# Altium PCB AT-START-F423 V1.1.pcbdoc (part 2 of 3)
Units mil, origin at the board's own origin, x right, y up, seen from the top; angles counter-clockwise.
Board outline 13392.89 x 3532.45 mil, 2 copper layers (Top Layer, Bottom Layer); 137 components, 162 nets, 618 pads, 618 vias.
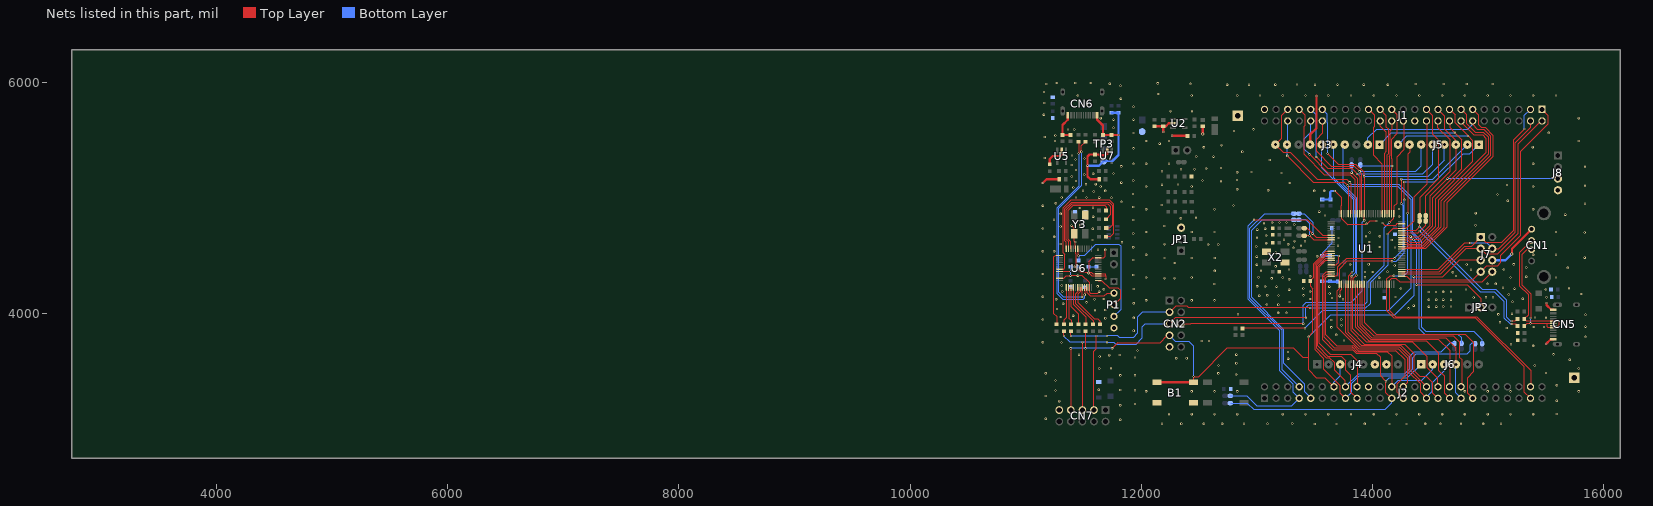
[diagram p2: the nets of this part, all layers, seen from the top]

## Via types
v1: diameter 19.68, hole 7.87, Top Layer to Bottom Layer, 317 vias
v2: diameter 19.7, hole 7.9, Top Layer to Bottom Layer, 187 vias
v3: diameter 19.7, hole 7.87, Top Layer to Bottom Layer, 72 vias
v4: diameter 27.56, hole 15.75, Top Layer to Bottom Layer, 31 vias
v5: diameter 23.62, hole 11.81, Top Layer to Bottom Layer, 11 vias

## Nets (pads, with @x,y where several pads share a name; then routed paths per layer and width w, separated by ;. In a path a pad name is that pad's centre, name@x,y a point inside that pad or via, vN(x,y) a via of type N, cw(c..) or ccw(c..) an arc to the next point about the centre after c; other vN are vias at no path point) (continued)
GND: B1.3 B1.4 C1.1 C2.1 C3.1 C7.1 C8.1 C9.1 C10.1 C11.1 C12.1 C14.1 C15.1 C16.1 C17.1 C18.1 C19.1 C20.1 C21.1 C22.1 C23.1 C24.1 C25.1 C26.1 C27.1 C29.1 C30.1 C31.1 C32.1 C33.1 C34.1 C35.1 C36.1 C37.1 C38.1 C39.1 CN1.4 CN2.9 CN5.A1B12 CN5.B1A12 CN6.A1B12 CN6.B1A12 CN7.9 D4.2 J1.24 J1.49 J2.20 J2.27 J3.7 J4.6 J4.7 J7.6 J8.4 JP1.3 LED1.2 P1.5 R2.1 R4.2 R7.1 R18.2 R19.2 R20.2 R21.2 R49.1 R51.1 R53.2 T1.1 T2.1 TP1.2 TP3.4 U1.20 U1.27 U1.74 U1.99 U2.2 U5.2 U6.8 U6.20 U6.23 U6.35 U6.39 U6.40 U6.47 U7.2 X2.2 X2.4 Y3.2 Y3.4 | length 7475.3
  Top Layer w6: U6.23@11292.68,4304.77 11327.37,4304.77 11350.28,4327.68 v1(11388.28,4327.68) v1(11451.38,4327.68) 11491.28,4327.68 11548.59,4270.36 U6.35@11548.58,4226.03 11548.59,4187.36 11559.28,4176.68 11623.28,4176.68 v1(11635.28,4188.68) ; U6.20@11292.68,4363.82 11388.13,4363.83 v1(11388.28,4363.68) ; U6.8@11430.47,4560.67 11430.48,4519.47 11434.28,4515.68 11434.28,4414.68 v1(11423.28,4403.68) 11476.28,4350.68 v5(11543.28,4350.68) ; v1(11689.28,4550.68) 11689.28,4495.68 11675.54,4481.94 U6.47@11627.32,4481.93 11579.54,4481.94 11543.28,4445.68 v5(11543.28,4350.68) ; v1(11690.28,4298.68) 11690.28,4324.46 ; v3(14085.58,4782.11) 14104.58,4763.11 14198.58,4763.11 14210.08,4774.61 U1.74@14251.67,4774.61 ; v5(11543.28,4350.68) 11569.5,4324.46 11627.32,4324.46 11690.28,4324.46 ; v5(11543.28,4350.68) 11573.28,4350.68 11579.82,4344.14 U6.40@11627.32,4344.14 11690.28,4344.14 11690.28,4324.46
  Top Layer w10: v1(11396.28,4759.68) 11421.04,4734.92 Y3.4@11421.04,4689.97 11421.04,4626.92 v1(11430.28,4617.68) 11430.48,4617.47 U6.8@11430.47,4560.67 ; U1.20@13641.48,4420.31 13683.77,4420.31 13707.58,4444.11 13707.58,4496.11 v1(13706.58,4497.11) ; v3(13671.58,5060.11) 13732.58,4999.11 13732.58,4934.11 13730.08,4931.61 U1.99@13730.08,4863.21 13730.08,4823.61 13784.58,4769.11 13944.58,4769.11 13974.58,4799.11 v2(14033.58,4799.11) ; v5(13715.58,4152.11) 13714.58,4153.11 13714.58,4191.11 13730.08,4206.61 U1.27@13730.08,4253.01
  Top Layer w20: v1(11148.28,5129.27) 11179.68,5160.68 C17.1@11290.72,5160.68 ; R51.1@11208.28,5290.34 11208.28,5336.68 11233.28,5361.68 11299.28,5361.68 11311.28,5373.68 U5.2@11311.28,5410.68 ; CN6.B1A12@11363.6,5715.38 11363.6,5675 11318.28,5629.68 C19.1@11318.28,5543.24 C18.1@11388.28,5543.24 ; CN6.A1B12@11617.4,5715.38 11617.4,5676.55 11668.28,5625.68 C15.1@11668.28,5543.24 C16.1@11743.28,5543.24 11802.84,5543.24 v1(11803.28,5543.68) ; C14.1@11635.72,5160.68 11560.28,5160.68 11535.28,5185.68 v1(11535.28,5278.32) 11535.28,5357.68 11552.94,5375.34 R49.1@11598.28,5375.34 11598.62,5375.68 11633.28,5375.68 11641.28,5367.68 11693.28,5367.68 11706.27,5380.67 U7.2@11706.27,5415.68 ; C1.1@12113.62,5618.94 C2.1@12188.62,5618.94 ; v3@12189.62,5570.16 C2.1@12189.62,5617.94 C2.1@12188.62,5618.94 ; v2(12264.58,5537.11) 12265.01,5536.68 R2.1@12398.62,5536.68 ; U2.2@12274.62,5644.5 12237.96,5644.5 12212.4,5618.94 C2.1@12188.62,5618.94 ; C3.1@12531.28,5618.12 12531.28,5553.41 v4(12531.58,5553.11) ; J3.7@13459.5,5460.43 13459.5,5547.04 13514.89,5602.43 v1(13514.89,5881.6) ; v4(15202.58,4515.11) 15204.58,4517.11 15204.58,4559.41 CN1.4@15374.55,4729.39 ; v2(15498.89,3736.6) 15540.41,3778.11 CN5.A1B12@15562.27,3778.11 ; v2(15503.89,4090.6) 15503.89,4072.6 15544.58,4031.91 CN5.B1A12@15562.27,4031.91
  Bottom Layer w6: v1(11388.28,4327.68) v1(11388.28,4363.68) C12.1@11388.28,4403.12 11422.72,4403.12 v1(11423.28,4403.68) 11457.72,4403.68 C22.1@11458.28,4403.12 ; v5(11543.28,4350.68) C9.1@11543.28,4403.12 C8.1@11613.28,4403.12
  Bottom Layer w10: C38.1@13563.58,4498.67 13563.58,4522.11 13647.01,4605.55 C39.1@13647.01,4741.11 ; C37.1@13631.58,4498.67 13705.01,4498.67 v1(13706.58,4497.11)
  Bottom Layer w20: v1(11535.28,5278.32) 11634.82,5278.32 TP3.4@11674.63,5318.13 11751.73,5318.13 11803.28,5369.68 v1(11803.28,5543.68) R21.2@11803.28,5736.02 R20.2@11743.28,5736.02 ; C36.1@13561.58,4277.55 C35.1@13629.58,4277.55 ; C38.1@13563.58,4498.67 C37.1@13631.58,4498.67 ; C30.1@13564.58,4985.67 C31.1@13634.58,4985.67 13632.58,4987.67 13632.58,5049.11 13643.58,5060.11 v3(13671.58,5060.11) ; C35.1@13630.58,4278.55 C35.1@13629.58,4277.55 ; C32.1@13701.01,4275.11 13632.01,4275.11 C35.1@13629.58,4277.55 ; J7.6@15034.51,4460.97 15148.44,4460.97 v4(15202.58,4515.11)
  other v1: 14146.88,3044.08 14292.94,3044.08 13498.88,3045.08 13686.88,3045.08 13930.88,3046.08 14453.88,3046.08 14587.77,3046.08 14764.88,3046.08 14955.88,3046.08 12177.88,3047.08 12345.88,3047.08 12540.33,3047.08 12699.21,3047.08 12887.88,3047.08 13090.68,3047.08 15109.88,3047.08 13304.88,3048.08 11817.88,3081.08 11173.28,3089.77 12238.67,3129.95 12435.52,3129.95 12632.37,3129.95 12829.22,3129.95 13222.92,3129.95 13419.77,3129.95 13616.62,3129.95 13813.47,3129.95 14010.32,3129.95 14207.17,3129.95 14404.02,3129.95 14600.87,3129.95 14797.72,3129.95 14994.58,3129.95 15191.43,3129.95 15388.28,3129.95 15591.89,3131.6 11817.88,3207.08 11944.88,3218.08 11290.38,3241.98 15591.89,3245.6 11173.28,3286.62 12041.82,3326.8 12238.67,3326.8 12435.52,3326.8 12632.37,3326.8 12829.22,3326.8 14797.72,3326.8 14994.58,3326.8 15191.43,3326.8 15781.98,3326.8 11257.88,3335.08 11944.88,3336.08 11818.88,3339.17 11631.53,3341.08 15592.89,3379.6 11257.88,3419.98 11818.88,3465.08 11944.88,3465.08 12819.89,3473.6 11173.28,3483.47 12665.89,3482.6 11635.88,3524.08 15781.98,3523.66 11736.89,3527.6 12666.89,3549.6 12821.89,3569.6 13269.89,3609.6 12301.89,3613.6 12391.89,3613.6 11945.88,3620.08 11639.88,3628.08 11722.88,3640.08 11813.88,3641.08 11460.88,3644.08 12821.89,3644.6 13268.89,3666.6 11967.88,3680.08 15388.28,3720.51 11309.88,3750.08 11148.28,3751.32 12522.89,3762.6 12585.89,3762.6 15840.89,3798.6 11933.88,3851.08 15393.89,3882.6 15480.89,3882.6 11148.28,3948.17 11689.28,3958.68 11933.88,3962.48 15498.89,3962.6 15404.89,3964.6 11304.28,3969.68 11410.28,3981.68 15840.89,3989.6 12836.89,3993.6 13182.89,4005.6 13255.89,4005.6 11600.28,4028.68 11689.28,4030.68 11270.28,4039.68 14309.89,4044.6 14354.89,4067.6 11324.28,4084.68 11934.88,4089.08 11525.28,4096.68 12041.82,4114.21 12435.52,4114.21 12632.37,4114.21 11263.28,4123.68 11594.28,4123.68 11676.28,4124.68 15297.89,4127.6 11148.28,4145.02 15802.89,4169.6 11316.28,4190.68 11676.28,4209.68 11934.88,4211.45 15225.89,4214.6 13400.58,4217.11 11622.28,4234.68 11312.28,4242.68 12630.89,4255.6 12041.82,4311.06 12435.52,4311.06 13222.92,4311.06 15191.43,4311.06 15585.13,4311.06 13012.89,4313.6 11930.88,4333.08 11148.28,4341.87 11929.88,4462.08 12435.89,4479.6 12633.89,4479.6 12041.82,4507.91 15388.28,4507.91 15585.13,4507.91 11148.28,4538.72 11246.28,4538.68 11625.28,4551.68 11929.88,4572.71 12664.89,4596.6 11303.28,4600.68 11832.28,4615.68 11577.38,4636.13 11246.28,4662.69 11929.88,4692.08 12041.82,4704.76 12435.52,4704.76 12632.37,4704.76 15585.13,4704.76 13002.58,4725.11 11580.28,4732.68 11148.28,4735.57 11302.28,4751.68 11472.78,4766.2 13322.58,4769.11 11929.88,4808.94 11244.28,4810.68 11583.28,4837.68 11302.28,4861.45 14890.89,4867.6 12041.82,4901.61 12632.37,4901.61 15388.28,4901.61 11468.58,4913.11 11581.58,4914.11 11930.88,4920.08 11148.28,4932.42 12796.89,4934.6 11261.28,4953.68 11828.28,4965.68 11741.58,5001.11 11636.58,5002.11 11434.58,5003.11 11526.58,5003.11 11311.28,5003.68 15079.89,5028.6 11928.88,5033.08 11588.28,5055.68 11689.28,5060.68 11496.28,5061.68 12828.89,5074.6 11412.28,5089.68 11648.12,5098.46 12041.82,5098.46 12435.52,5098.46 15388.28,5098.46 15161.89,5111.6 11521.28,5116.68 11605.28,5118.68 13283.89,5127.6 11827.28,5131.68 11434.28,5146.68 11929.88,5150.08 11398.28,5185.68 11506.28,5201.68 11583.28,5208.68 11759.28,5210.68 11434.28,5240.84 11826.28,5272.68 11398.28,5283.68 11932.88,5294.08 12041.82,5295.31 12238.67,5295.31 15388.28,5295.31 13109.58,5327.11 11430.28,5332.68 11509.28,5339.68 11163.89,5345.6 11400.28,5366.68 11932.88,5428.08 11254.42,5492.16 12041.82,5492.16 12238.67,5492.16 15781.98,5492.16 11163.89,5525.6 11256.28,5539.68 11932.88,5560.94 11366.28,5590.68 11419.64,5590.68 11759.25,5606.03 11931.88,5676.08 11759.25,5676.58 11648.12,5689.01 15781.98,5689.01 11156.89,5719.6 11931.88,5788.08 11160.89,5820.6 11823.28,5857.68 11451.27,5885.86 12435.52,5885.86 12829.22,5885.86 13026.07,5885.86 13222.92,5885.86 13419.77,5885.86 13616.62,5885.86 13813.47,5885.86 14010.32,5885.86 14207.17,5885.86 14404.02,5885.86 14600.87,5885.86 14797.72,5885.86 14994.58,5885.86 15191.43,5885.86 15388.28,5885.86 15585.13,5885.86 12145.58,5898.11 11157.89,5915.6 11819.28,5969.68 12741.88,5979.08 12931.88,5979.08 13158.88,5979.08 13500.88,5979.08 13696.88,5979.08 13922.96,5979.08 14131.88,5979.08 13346.88,5981.08 11178.28,5983.68 14372.88,5984.08 14614.8,5984.08 14812.88,5984.08 15038.88,5984.08 12425.13,5986.13 11727.28,5986.68 12141.88,5990.08 11429.28,5992.68 11563.56,5992.68 11269.28,5993.68
  other v2: 15498.58,3486.11 15401.58,3550.11 15704.58,3600.11 15563.58,3647.11 15196.58,3734.11 13751.89,3766.6 13685.89,3815.6 15158.89,3874.6 13642.89,3880.6 15840.58,3886.11 13730.89,3898.6 15100.89,3923.6 13641.89,3944.6 13728.89,3948.6 15086.89,3992.6 15204.89,3998.6 14485.89,4059.6 14549.89,4059.6 14610.89,4060.6 14677.89,4060.6 13184.58,4076.11 13085.58,4078.11 13280.58,4099.11 15209.89,4101.6 14485.89,4118.6 14549.89,4118.6 14610.89,4119.6 14677.89,4119.6 13744.58,4123.11 13459.58,4125.11 13647.89,4133.6 14873.89,4138.6 14979.89,4139.6 15040.89,4140.6 15503.89,4140.6 14197.89,4142.6 13019.89,4153.6 13186.58,4155.11 13402.58,4157.11 13088.58,4158.11 15176.89,4164.6 13628.58,4172.11 14484.89,4186.6 14548.89,4186.6 14609.89,4187.6 14676.89,4187.6 13459.58,4190.42 13278.58,4206.68 14807.89,4207.6 15497.89,4208.6 14243.89,4216.6 15697.89,4219.6 15126.89,4222.6 13169.58,4232.11 13625.58,4232.11 13070.37,4233.11 13001.89,4234.6 14992.89,4256.6 15063.89,4256.6 13278.58,4296.11 13126.58,4304.11 12201.04,4306.11 12287.58,4306.11 14056.58,4309.11 13934.01,4312.5 15328.58,4317.69 13459.58,4322.11 14720.89,4324.6 14693.89,4356.6 13934.01,4358.11 14001.58,4358.11 14129.58,4361.11 12633.89,4368.6 13035.58,4369.11 14850.89,4378.6 13276.58,4380.11 15134.58,4380.11 15687.58,4395.11 15328.58,4398.11 13161.88,4408.18 14190.58,4415.11 12998.89,4422.6 13805.58,4424.11 14812.89,4424.6 15220.58,4425.11 13965.58,4426.11 12289.58,4436.11 12200.58,4479.11 15833.7,4482.65 12997.89,4491.6 13520.58,4495.11 13161.58,4526.11 13315.58,4568.11 14193.58,4571.11 14062.58,4575.84 12993.89,4578.6 13935.58,4581.11 13381.58,4585.11 13700.89,4585.6 12577.89,4596.6 13269.58,4599.11 12199.58,4600.11 13079.58,4608.11 13969.89,4618.6 13415.58,4625.11 13323.89,4625.6 14164.58,4636.11 13233.58,4638.11 13704.58,4652.11 12999.89,4654.6 14062.58,4668.11 13941.89,4668.6 13079.58,4674.29 15833.7,4699.98 13974.89,4700.6 13070.89,4733.6 12198.58,4756.11 14889.89,4763.6 13947.58,4775.11 13060.58,4781.11 13131.31,4786.11 13194.65,4786.11 13255.58,4786.11 12341.58,4824.11 12473.58,4827.11 14229.58,4839.11 13587.89,4847.6 15665.98,4854.81 13538.89,4880.6 14228.58,4903.11 12176.58,4939.11 15836.58,4949.11 15168.58,4975.11 13495.89,5060.6 13580.89,5060.6 13096.89,5065.6 15836.58,5104.17 12178.58,5114.11 12316.58,5115.11 12688.58,5144.11 12529.58,5150.11 12827.89,5154.6 13212.58,5215.11 12828.58,5221.11 12952.89,5223.6 12178.58,5230.11 12343.58,5247.11 12460.27,5247.11 12560.58,5253.11 12689.89,5257.6 15836.58,5268.11 12624.58,5356.11 12474.58,5358.11 12873.58,5399.11 12540.58,5437.11 15383.58,5438.11 12692.58,5456.11 12158.89,5468.6 15522.58,5562.11 12800.89,5577.6 12970.58,5592.11 12252.58,5750.11 12437.56,5750.11
  other v3: 12189.58,5570.11
LD1: LD1.2 U6.10 | length 724.3
  Top Layer w6: U6.10@11391.1,4560.67 11391.11,4620.57 11367.58,4644.11 11367.58,4893.11 11409.58,4935.11 11681.84,4935.11 11695.05,4921.91 LD1.2@11695.05,4890.13
LD2: LD2.2 U6.11 | length 882.4
  Top Layer w6: U6.11@11371.42,4560.67 11371.42,4619.26 11352.58,4638.11 11352.58,4899.11 11402.58,4949.11 11709.84,4949.11 11733.28,4925.68 11733.28,4853.3 LD2.2@11696.01,4816.03
LD3: LD3.2 U6.12 | length 1032.8
  Top Layer w6: U6.12@11351.73,4560.67 11351.74,4616.94 11337.58,4631.11 11337.58,4905.11 11396.58,4964.11 11720.84,4964.11 11747.58,4937.38 11747.58,4762.97 11722.28,4737.68 11697.5,4737.68 LD3.2@11696.05,4739.13
LD4: LD4.2 U6.19 | length 1384.7
  Top Layer w6: U6.19@11292.68,4383.51 11327.11,4383.51 11339.28,4395.68 11339.28,4513.68 11322.58,4530.38 11322.58,4910.11 11391.58,4979.11 11728.58,4979.11 11761.58,4946.11 11761.58,4693.97 11730.73,4663.13 LD4.2@11696.01,4663.13
M-ATLK_RX: R48.1 U6.31 | length 427.7
  Top Layer w6: U6.31@11469.85,4226.03 11469.85,4187.56 11448.89,4166.6 11448.89,4098.6 11592.89,3954.6 11624.36,3954.6 11644.28,3934.68 R48.1@11644.28,3906.34
M-ATLK_TX: R47.1 U6.30 | length 392
  Top Layer w6: U6.30@11450.16,4226.03 11450.16,4189.87 11428.89,4168.6 11428.89,4089.84 11582.28,3936.46 R47.1@11582.28,3906.34
M-NRST: C22.2 P1.4 U6.7 | length 1152.1
  Top Layer w6: U6.7@11450.16,4560.67 11450.16,4506.79 v1(11457.28,4499.68)
  Bottom Layer w6: C22.2@11458.28,4458.24 11458.28,4498.68 v1(11457.28,4499.68) 11506.28,4499.68 11603.28,4596.68 11809.28,4596.68 11826.28,4579.68 11826.28,4038.68 P1.4@11763.28,3975.68
M-SWCLK: P1.3 U6.37 | length 372.6
  Top Layer w6: U6.37@11627.32,4285.08 11658.87,4285.09 11721.28,4222.68 11797.28,4222.68 11816.28,4203.68 11816.28,4128.68 P1.3@11763.28,4075.68
M-SWDIO: P1.2 U6.34 | length 299.5
  Top Layer w6: U6.34@11528.9,4226.03 11528.9,4183.05 11559.28,4152.68 11680.92,4152.68 11703.92,4175.68 P1.2@11763.28,4175.68
M-USB_D+: R11.2 U6.33 | length 1747.5
  Top Layer w6: v1(11457.28,5382.68) 11458.28,5383.68 R11.2@11458.28,5486.02 ; U6.33@11509.21,4226.03 11509.22,4165.73 11510.28,4164.68 v1(11510.28,4162.68)
  Bottom Layer w6: v1(11457.28,5382.68) 11457.28,5101.81 11267.28,4911.81 11267.28,4176.68 11319.1,4124.85 11498.31,4124.85 11510.28,4136.81 v1(11510.28,4162.68)
M-USB_D-: R12.2 U6.32 | length 1709.5
  Top Layer w6: v1(11481.28,5398.68) 11481.28,5449.02 R12.2@11518.28,5486.02 ; U6.32@11489.53,4226.03 v1@11489.53,4143.68 ; v1@11489.53,4143.68 11488.28,4143.19 11489.53,4141.93 v1@11489.53,4143.68
  Bottom Layer w6: v1(11481.28,5398.68) 11481.28,5106.02 11281.28,4906.02 11281.28,4186.68 11324.28,4143.68 v1(11488.28,4143.68)
M_ATLK_BOOT0: R45.1 U6.27 | length 346.3
  Top Layer w6: U6.27@11391.1,4226.03 11391.11,4062.84 11455.28,3998.68 R45.1@11455.28,3906.34
M_ATLK_NRST: R46.1 U6.28 | length 364.2
  Top Layer w6: U6.28@11410.79,4226.03 11410.79,4080.16 11518.28,3972.68 R46.1@11518.28,3906.34
M_ATLK_SWCLK: R41.1 U6.25 | length 328.6
  Top Layer w6: R41.1@11330.28,3906.34 11330.28,3942.68 11351.74,3964.14 U6.25@11351.73,4226.03
M_ATLK_SWDIO: R44.1 U6.26 | length 328.3
  Top Layer w6: U6.26@11371.42,4226.03 11371.42,3960.53 11392.28,3939.68 R44.1@11392.28,3906.34
M_ATLK_SWO: R52.1 U6.13 | length 652
  Top Layer w6: R52.1@11268.28,3906.34 11268.28,3974.68 11239.28,4003.68 11239.28,4486.68 11254.23,4501.63 U6.13@11292.68,4501.62
NRST: B1.1 B1.2 C27.2 CN2.7 CN7.7 J2.14 J4.3 J7.5 R46.2 U1.14 | length 7105.6
  Top Layer w6: v1(11389.88,3699.08) v1@11390.38,3699.58 ; v1@11389.88,3701.58 11389.88,3697.58 v1@11390.38,3697.08 ; CN7.7@11390.38,3165.68 v1@11390.38,3697.08 ; v1@11390.38,3701.58 v1@11390.38,3697.08 ; v1(11516.88,3699.08) 11517.88,3700.08 11517.88,3846.62 R46.2@11518.28,3847.02 ; v2(11748.05,3699.08) 11797.32,3748.34 12161.51,3748.34 12218.81,3805.64 12238.25,3805.64 CN2.7@12244.28,3811.68 ; v2(12450.89,3454.6) v2@12451.06,3454.6 ; B1.2@12451.06,3404.69 v2@12451.06,3454.6 ; v3@13445.58,3798.88 13445.58,3618.38 ; v3(13445.89,3798.6) 13483.42,3836.13 13483.42,4216.26 13459.14,4240.55 C27.2@13459.14,4282.11 13484.58,4307.55 13484.58,4428.11 13594.88,4538.41 U1.14@13641.48,4538.41 ; J2.14@13665.15,3366.57 13585.61,3446.11 13514.58,3446.11 13445.58,3515.11 13445.58,3618.38 ; v2(14353.89,4318.6) 14607.89,4318.6 14750.27,4460.97 J7.5@14934.51,4460.97 ; v2@12451.06,3454.6 12494.89,3454.6 12739.89,3699.6 13317.89,3699.6 13399.11,3618.38 13445.58,3618.38
  Top Layer w20: B1.1@12136.09,3404.69 B1.2@12451.06,3404.69
  Bottom Layer w6: v1(11389.88,3699.08) v1(11516.88,3699.08) v2(11748.05,3699.08) ; CN2.7@12244.28,3811.68 12294.36,3761.6 12408.89,3761.6 12450.89,3719.6 v2(12450.89,3454.6) ; v3(13445.89,3798.6) 13636.41,3989.11 14191.41,3989.11 14353.89,4151.6 v2(14353.89,4318.6) ; J2.14@13665.15,3366.57 13665.15,3406.69 13719.5,3461.04 J4.3@13719.5,3560.43
OTGFS1_D+: CN1.3 CN5.A6 CN5.B6 R54.2 | length 1152.5
  Top Layer w6: CN1.3@15374.55,4630.96 15266.89,4523.31 15266.89,4241.6 15343.89,4164.6 15343.89,3985.77 R54.2@15312.24,3954.11 15331.74,3934.61 CN5.B6@15562.27,3934.61 15603.88,3934.61 15610.89,3927.6 15610.89,3902.93 15603.28,3895.31 CN5.A6@15562.27,3895.31
OTGFS1_D-: CN1.2 CN5.A7 CN5.B7 R55.2 | length 1075.9
  Top Layer w6: R55.2@15312.24,3892.11 15335.03,3914.91 v2(15365.91,3914.91) 15510.08,3914.91 ; v2(15365.89,3960.6) 15365.89,4171.6 15288.89,4248.6 15288.89,4509.6 15331.52,4552.22 CN1.2@15374.55,4552.22 ; CN5.B7@15562.27,3875.61 15518.88,3875.61 15509.89,3884.6 15509.89,3914.72 15510.08,3914.91 ; CN5.A7@15562.27,3914.91 15510.08,3914.91
  Bottom Layer w6: v2(15365.91,3914.91) v2(15365.89,3960.6)
PA0: J2.23 J6.1 R5.1 U1.23 | length 3444.6
  Top Layer w6: U1.23@13641.48,4361.31 13599.77,4361.31 13568.58,4330.11 13568.58,3771.11 13654.53,3685.16 13829.53,3685.16 13862.59,3652.1 14037.59,3652.1 14068.58,3621.11 14068.58,3460.11 14114.79,3413.9 v3(14115.58,3413.9) 14115.58,3316.14 J2.23@14165.15,3266.57
  Bottom Layer w6: R5.1@12772.24,3226.11 12916.58,3226.11 12971.58,3171.11 14108.58,3171.11 14165.15,3227.69 J2.23@14165.15,3266.57 ; v3(14115.58,3413.9) 14139.79,3438.11 14297.17,3438.11 J6.1@14419.48,3560.43
PA1: J2.24 J6.2 U1.24 | length 1974.7
  Top Layer w6: U1.24@13641.48,4341.61 13602.08,4341.61 13582.58,4322.11 13582.58,3793.11 13669.58,3706.11 13828,3706.11 13828.18,3706.3 13868.39,3666.1 14131.59,3666.1 14168.58,3629.11 14168.58,3369.99 J2.24@14165.15,3366.57
  Bottom Layer w6: J2.24@14165.15,3366.57 14219.69,3421.11 14424.58,3421.11 14519.48,3516.02 J6.2@14519.48,3560.43
PA2: J2.25 J5.2 U1.25 | length 3769.1
  Top Layer w6: v3(14188.58,4477.11) 14186.58,4475.11 13771.58,4475.11 13695.58,4399.11 13695.58,4332.11 13685.38,4321.91 U1.25@13641.48,4321.91 13607.38,4321.91 13596.58,4311.11 13596.58,3815.11 13688.58,3723.11 13830.29,3723.11 13830.73,3723.55 13874.19,3680.1 14198.59,3680.1 14280.58,3598.11 14280.58,3462.11 14211.58,3393.11 14211.58,3320.14 J2.25@14265.15,3266.57 ; v3(14247.58,4952.11) v3(14247.58,5162.11)
  Bottom Layer w6: v3(14188.58,4477.11) 14261.58,4550.11 14261.58,4938.11 v3(14247.58,4952.11) ; v3(14247.58,5162.11) 14520.58,5162.11 14818.89,5460.43 J5.2@14819.51,5460.43
PA3: J2.26 J5.1 U1.26 | length 3509.7
  Top Layer w6: v3(14167.58,4451.11) 14166.58,4450.11 13776.58,4450.11 13710.38,4383.91 U1.26@13710.38,4253.01 13710.38,4212.91 13688.58,4191.11 13688.58,3885.51 13879.99,3694.1 14222.59,3694.1 14298.58,3618.11 14298.58,3399.99 J2.26@14265.15,3366.57 ; v3(14274.58,5138.11) 14274.58,4984.11 v3(14275.58,4983.11)
  Bottom Layer w6: v3(14167.58,4451.11) 14202.58,4451.11 14275.58,4524.11 v3(14275.58,4983.11) ; v3(14274.58,5138.11) 14537.58,5138.11 14781.58,5382.11 14841.19,5382.11 J5.1@14919.51,5460.43
PA4: J2.29 J6.3 U1.29 | length 1832.8
  Top Layer w6: U1.29@13769.38,4253.01 13769.38,3833.31 13894.58,3708.11 14236.59,3708.1 14318.58,3626.11 14318.58,3489.11 14414.58,3393.11 14414.58,3317.14 J2.29@14465.15,3266.57
  Bottom Layer w6: J2.29@14465.15,3266.57 14465.15,3277.69 14512.58,3325.11 14512.58,3396.11 14619.48,3503.02 J6.3@14619.48,3560.43
PA5: J2.30 J3.6 U1.30 | length 2709.3
  Top Layer w6: v3(13821.58,4355.11) 13789.08,4322.61 U1.30@13789.08,4253.01 13789.08,3839.61 13906.58,3722.11 14249.59,3722.1 14335.58,3636.11 14335.58,3501.11 14465.15,3371.54 J2.30@14465.15,3366.57
  Bottom Layer w6: J3.6@13559.5,5460.43 13559.5,5260.59 13836.58,4983.51 13836.58,4370.11 v3(13821.58,4355.11)
PA6: J2.31 J3.5 U1.31 | length 2841.9
  Top Layer w6: v3(13820.58,4322.11) 13808.77,4310.31 U1.31@13808.77,4253.01 13808.77,3853.91 13926.57,3736.12 14276.59,3736.1 14356.58,3656.11 14356.58,3508.11 14408.73,3455.96 14465.5,3455.96 14515.58,3405.88 14515.58,3316.14 J2.31@14565.15,3266.57
  Bottom Layer w6: J3.5@13659.5,5460.43 13659.5,5180.39 13850.58,4989.31 13850.58,4352.11 v3(13820.58,4322.11)
PA7: J2.32 J3.4 U1.32 | length 2703.6
  Top Layer w6: v3(13860.58,4331.11) 13828.48,4299.01 U1.32@13828.48,4253.01 13828.48,3869.21 13947.57,3750.12 14346.59,3750.1 14470.58,3626.11 14470.58,3533.11 14565.15,3438.54 J2.32@14565.15,3366.57
  Bottom Layer w6: J3.4@13759.5,5460.43 13744.58,5445.5 13744.58,5115.11 13864.58,4995.11 13864.58,4335.11 v3(13860.58,4331.11)
PA8: J1.17 J5.8 U1.67 | length 2224.5
  Top Layer w6: U1.67@14251.67,4636.81 14301.68,4636.81 14320.89,4617.6 14408.89,4617.6 14546.58,4755.28 14546.58,4994.11 14867.58,5315.11 14867.58,5494.11 v3@14826.36,5535.33 ; J1.17@14665.15,5765.15 14713.58,5716.73 14713.58,5648.11 v3@14826.36,5535.33 ; v3(14825.58,5535.11) 14826.14,5535.11 v3@14826.36,5535.33
  Bottom Layer w6: J5.8@14219.51,5460.43 14294.19,5535.11 v3(14825.58,5535.11)
PA9: J1.18 J3.1 JP2.2 U1.68 | length 3143.6
  Top Layer w6: U1.68@14251.67,4656.51 14305.98,4656.51 14321.89,4640.6 v2(14352.43,4640.6) 14403.89,4640.6 14520.58,4757.28 14520.58,5003.11 14769.58,5252.11 14769.58,5504.46 v3@14711.92,5562.11 ; v2(14378.89,4249.6) 14818.89,4249.6 14934.89,4133.6 JP2.2@14934.89,4068.6 ; J1.18@14665.15,5665.15 14665.15,5608.89 v3@14711.92,5562.11 ; v3(14711.58,5562.11) v3@14711.92,5562.11
  Bottom Layer w6: J3.1@14059.5,5460.43 14161.18,5562.11 v3(14711.58,5562.11) ; v2(14352.43,4640.6) 14378.89,4614.13 v2(14378.89,4249.6)
PA10: J1.19 J5.3 J8.3 R9.2 U1.69 | length 4450.8
  Top Layer w6: R9.2@12874.21,3870.6 12876.21,3872.6 v3(13414.89,3872.6) ; U1.69@14251.67,4676.21 14313.28,4676.21 14324.89,4664.6 v3(14328.89,4664.6) 14400.89,4664.6 14497.58,4761.28 14497.58,5017.11 v3(14646.58,5166.11) 14719.51,5239.04 J5.3@14719.51,5460.43 14719.51,5500.18 14624.65,5595.04 14624.65,5705.65 J1.19@14565.15,5765.15
  Bottom Layer w6: v3(13414.89,3872.6) 13570.41,4028.11 14137.58,4028.11 14328.89,4219.43 v3(14328.89,4664.6) ; v3(14646.58,5166.11) J8.3@15602.58,5166.11
PA11: R32.2 R55.1 U1.70 | length 1541.9
  Top Layer w6: U1.70@14251.67,4695.91 14389.38,4695.91 v2(14406.88,4713.41) 14458.58,4765.11 R32.2@14458.58,4800.83 ; v2(15203.89,3909.6) 15235.43,3909.6 R55.1@15252.92,3892.11
  Bottom Layer w6: v2(14406.88,4713.41) 14931.7,4188.6 15052.89,4188.6 15133.89,4107.6 15133.89,3963.6 15187.89,3909.6 v2(15203.89,3909.6)
PA11_E: J1.20 R32.1 | length 951.4
  Top Layer w6: R32.1@14458.58,4845.23 14458.58,5019.11 14670.58,5231.11 14670.58,5502.11 14565.15,5607.54 J1.20@14565.15,5665.15
PA12: R33.2 R54.1 U1.71 | length 1497.7
  Top Layer w6: U1.71@14251.67,4715.61 14372.08,4715.61 v2(14405.58,4749.11) R33.2@14405.58,4800.83 ; v2(15202.89,3935.6) 15234.4,3935.6 R54.1@15252.92,3954.11
  Bottom Layer w6: v2(14405.58,4749.11) 14946.09,4208.6 15062.89,4208.6 15153.89,4117.6 15153.89,3970.46 15188.76,3935.6 v2(15202.89,3935.6)
PA12_E: J1.21 R33.1 | length 1031.1
  Top Layer w6: R33.1@14405.58,4845.23 14405.58,5002.11 14569.58,5166.11 14569.58,5502.11 14516.58,5555.11 14516.58,5713.73 J1.21@14465.15,5765.15
PA13/SWDIO: CN2.3 CN7.3 J1.22 R44.2 U1.72 | length 5352.6
  Top Layer w6: v1(11391.88,3805.08) 11391.88,3846.62 R44.2@11392.28,3847.02 ; CN7.3@11590.38,3165.68 11590.38,3675.58 11611.88,3697.08 v1(11611.88,3805.08) ; CN2.3@12244.28,4011.68 12295.71,4063.11 12395.58,4063.11 12410.58,4048.11 v3(13457.58,4048.11) ; v3(14129.58,4688.11) 14176.77,4735.31 U1.72@14251.67,4735.31 14291.26,4735.31 14355.89,4799.94 14355.89,5004.43 14469.58,5118.11 14469.58,5660.73 J1.22@14465.15,5665.15
  Bottom Layer w6: v1(11391.88,3805.08) v1(11611.88,3805.08) 11698.88,3805.08 11699.88,3806.08 11796.61,3806.08 11811.61,3791.08 11929.17,3791.08 11966.58,3828.48 11966.58,3969.11 12009.14,4011.68 CN2.3@12244.28,4011.68 ; v3(13457.58,4048.11) 13941.54,4048.11 13979.58,4086.14 13979.58,4268.11 14129.58,4418.11 v3(14129.58,4688.11)
  other v1: 11702.88,3806.08
PA14/SWCLK: CN2.5 CN7.5 J1.26 R41.2 U1.76 | length 5236.4
  Top Layer w6: R41.2@11330.28,3847.02 11330.28,3805.68 11330.68,3806.08 v1(11330.88,3806.08) ; CN7.5@11490.38,3165.68 11490.38,3751.58 v1(11490.88,3752.08) ; CN2.5@12244.28,3911.68 12294.71,3962.11 12386.58,3962.11 12387.06,3962.6 v3(13423.89,3962.6) ; v3(14143.58,4786.11) 14182.77,4825.31 U1.76@14182.77,4863.21 14182.77,4925.89 14207.58,4950.69 14207.58,5352.1 14269.58,5414.1 14269.58,5660.73 J1.26@14265.15,5665.15
  Bottom Layer w6: v1(11330.88,3806.08) 11330.88,3805.08 11383.88,3752.08 v1(11490.88,3752.08) v1(11702.88,3752.08) 11762.47,3752.08 11778.43,3736.11 11954.58,3736.11 12009.58,3791.11 12009.58,3886.11 12035.14,3911.68 CN2.5@12244.28,3911.68 ; v3(13423.89,3962.6) 13423.89,4051.43 13448.58,4076.11 13928.25,4076.11 13948.58,4096.44 13948.58,4266.11 14097.58,4415.11 14097.58,4739.11 14143.58,4785.11 v3(14143.58,4786.11)
PA15: J1.27 R39.2 U1.77 | length 1220.6
  Top Layer w6: U1.77@14163.08,4863.21 14163.08,5255.28 14168.58,5260.78 v3(14168.58,5276.11) 14168.58,5332.23 14164.58,5336.23 14164.58,5508.11 14213.58,5557.11 14213.58,5716.73 J1.27@14165.15,5765.15
  Bottom Layer w6: R39.2@13894.88,5274.42 14166.88,5274.42 v3(14168.58,5276.11)
PB0: J2.35 J6.4 U1.35 | length 1728
  Top Layer w6: U1.35@13887.48,4253.01 13887.48,3898.21 13993.57,3792.11 14630.59,3792.1 14719.48,3703.2 J6.4@14719.48,3560.43
  Bottom Layer w6: J6.4@14719.48,3560.43 14713.58,3554.52 14713.58,3318.14 J2.35@14765.15,3266.57
PB1: J2.36 U1.36 | length 1648.5
  Top Layer w6: U1.36@13907.17,4253.01 13907.17,3908.51 14009.58,3806.11 14697.5,3806.11 14748.58,3755.04 14748.58,3623.55 14769.58,3602.55 14769.58,3370.99 J2.36@14765.15,3366.57
PB2: J2.37 U1.37 | length 1868.9
  Top Layer w6: U1.37@13926.88,4253.01 13926.88,3925.81 14032.58,3820.11 14800.58,3820.11 14869.58,3751.11 14869.58,3495.11 14816.58,3442.11 14816.58,3315.14 J2.37@14865.15,3266.57
PB3/SWO: CN2.6 J1.39 J5.4 U1.89 | length 4479.5
  Top Layer w6: CN2.6@12344.28,3911.68 12429.14,3911.68 12429.22,3911.6 v3(13399.89,3911.6) ; v3(13610.58,5383.11) 13705.58,5288.11 13858.58,5288.11 13925.58,5221.11 v3(13925.58,5186.11) U1.89@13925.58,4864.51 ; U1.89@13926.88,4863.21 13926.88,4806.81 v3(13927.58,4806.11)
  Bottom Layer w6: v3(13399.89,3911.6) 13399.89,4071.43 13427.58,4099.11 13813.58,4099.11 13905.58,4191.11 13905.58,4784.11 v3(13927.58,4806.11) ; J1.39@13565.15,5765.15 13605.65,5724.65 13605.65,5648.38 13610.58,5643.45 v3(13610.58,5383.11) ; v3(13925.58,5186.11) 14482,5186.11 14619.51,5323.62 J5.4@14619.51,5460.43
PB4: J1.40 J5.6 U1.90 | length 1839.2
  Top Layer w6: J1.40@13565.15,5665.15 13565.15,5557.69 13511.58,5504.11 13511.58,5407.11 13648.58,5270.11 13846.58,5270.11 v3(13887.58,5229.11) 13902.58,5214.11 13902.58,5150.55 13907.17,5145.95 U1.90@13907.17,4863.21
  Bottom Layer w6: v3(13887.58,5229.11) 14371.58,5229.11 14419.51,5277.04 J5.6@14419.51,5460.43
PB5: J1.41 J5.5 U1.91 | length 2056.2
  Top Layer w6: v3(13511.58,5354.11) 13615.58,5250.11 13822.58,5250.11 v3(13865.58,5207.11) 13887.48,5185.21 U1.91@13887.48,4863.21
  Bottom Layer w6: J1.41@13465.15,5765.15 13511.58,5718.73 v3(13511.58,5354.11) ; v3(13865.58,5207.11) 14435.58,5207.11 14519.51,5291.04 J5.5@14519.51,5460.43
PB6: J1.42 R38.2 U1.92 | length 1201.4
  Top Layer w6: v3(13454.58,5376.11) 13612.58,5218.11 v3(13818.58,5218.11) 13818.58,5217.11 13867.88,5167.81 U1.92@13867.88,4863.21
  Bottom Layer w6: v3(13454.58,5376.11) 13409.58,5421.11 13409.58,5512.11 13465.15,5567.69 J1.42@13465.15,5665.15 ; R38.2@13817.88,5283.8 13817.88,5218.81 v3(13818.58,5218.11)
PB7: J1.43 U1.93 | length 1237.9
  Top Layer w6: J1.43@13365.15,5765.15 13415.58,5714.73 13415.58,5628.11 13408.58,5621.11 13408.58,5375.11 13587.58,5196.11 13809.58,5196.11 13848.17,5157.51 U1.93@13848.17,4863.21
PB8: J1.45 J3.10 R36.2 U1.95 | length 3750.6
  Top Layer w6: J1.45@13265.15,5765.15 13214.58,5714.58 13214.58,5515.5 J3.10@13159.5,5460.43 13159.5,5460.19 13229.44,5390.25 13291.44,5390.25 13523.58,5158.11 13778.58,5158.11 v3(13802.58,5134.11) 13808.77,5127.91 U1.95@13808.77,4863.21
  Bottom Layer w6: v3(13802.58,5134.11) 13821.58,5115.11 14229.38,5115.11 14348.89,4995.6 14348.89,4702.6 14424.89,4626.6 14424.89,3881.6 14464.89,3841.6 14879.09,3841.6 14946.58,3774.11 R36.2@14946.58,3739.23
PB9: J1.46 J3.9 R35.2 U1.96 | length 3373.5
  Top Layer w6: v3(13262.58,5363.11) 13488.58,5137.11 13755.58,5137.11 13788.08,5104.61 v3@13789.08,5104.61 ; U1.96@13789.08,4863.21 v3@13789.08,5104.61 ; v3@13789.08,5107.11 v3@13789.08,5104.61
  Bottom Layer w6: v3(13262.58,5363.11) 13262.58,5457.36 J3.9@13259.5,5460.43 13265.15,5466.08 J1.46@13265.15,5665.15 ; v3(13784.58,5107.11) 13796.58,5095.11 14220.38,5095.11 14331.89,4983.6 14331.89,4696.6 14402.89,4625.6 14402.89,3867.71 14453.01,3817.6 14740.89,3817.6 14768.58,3789.91 R35.2@14768.58,3741.23
PB10: J2.47 J5.7 U1.47 | length 3273.1
  Top Layer w6: v3(14183.58,4326.11) 14181.58,4324.11 14147.58,4324.11 14123.77,4300.31 U1.47@14123.77,4253.01 14123.77,4024.91 14188.58,3960.11 14892.98,3960.11 15311.58,3541.51 15311.58,3320.14 J2.47@15365.15,3266.57 ; v3@14301.58,4866.11 14301.58,5377.11 14319.51,5395.04 J5.7@14319.51,5460.43
  Bottom Layer w6: v3(14183.58,4326.11) 14269.58,4326.11 14301.58,4358.11 v3(14301.58,4867.11)
PB11: J2.48 J7.8 U1.48 | length 2780.3
  Top Layer w6: J7.8@15034.51,4360.97 14947.13,4273.6 14232.89,4273.6 14204.38,4302.11 14160.58,4302.11 14143.48,4285.01 U1.48@14143.48,4253.01 14143.48,4030.01 14199.38,3974.11 14898.78,3974.11 15365.15,3507.74 J2.48@15365.15,3366.57
PB12: J1.1 J7.7 U1.51 | length 2444.1
  Top Layer w6: U1.51@14251.67,4321.91 14294.58,4321.91 14323.89,4292.6 14866.13,4292.6 J7.7@14934.51,4360.97 14982.65,4409.11 15076.58,4409.11 15104.75,4437.29 15104.75,4501.14 15276.58,4672.96 15276.58,5398.11 15515.58,5637.11 15515.58,5714.73 J1.1@15465.15,5765.15
PB13: J1.2 J7.3 U1.52 | length 2255.2
  Top Layer w6: U1.52@14251.67,4341.61 14584.91,4341.61 14804.27,4560.97 J7.3@14934.51,4560.97 14984.37,4511.11 15076.58,4511.11 15255.58,4690.11 15255.58,5462.11 15458.61,5665.15 J1.2@15465.15,5665.15
PB14: J1.3 J7.1 U1.53 | length 2262.3
  Top Layer w6: U1.53@14251.67,4361.31 14577.61,4361.31 14798.17,4581.87 14855.4,4581.87 J7.1@14934.51,4660.97 14983.37,4612.11 15111.58,4612.11 15214.58,4715.11 15214.58,5497.11 v3(15312.58,5595.11)
  Bottom Layer w6: v3(15312.58,5595.11) 15312.58,5712.58 J1.3@15365.15,5765.15
PB15: J1.4 J7.4 U1.54 | length 2173.6
  Top Layer w6: U1.54@14251.67,4380.91 14568.21,4380.91 14797.89,4610.6 v2(14844.89,4610.6) ; J7.4@15034.51,4560.97 15092.44,4560.97 15233.58,4702.11 15233.58,5478.11 15365.15,5609.69 J1.4@15365.15,5665.15
  Bottom Layer w6: v2(14844.89,4610.6) 14984.89,4610.6 J7.4@15034.51,4560.97
PC0: J2.15 R37.2 U1.15 | length 2900.1
  Top Layer w6: U1.15@13641.48,4518.71 13594.98,4518.71 13498.58,4422.31 13498.58,3690.11 13573.58,3615.11 13573.58,3522.11 13714.58,3381.11 13714.58,3316.11 13764.12,3266.57 J2.15@13765.15,3266.57
  Bottom Layer w6: J2.15@13765.15,3266.57 13814.58,3315.99 13814.58,3393.11 13879.58,3458.11 14283.58,3458.11 14342.58,3517.11 14342.58,3615.11 14374.58,3647.11 14813.58,3647.11 14839.58,3673.11 14839.58,3724.11 14859.24,3743.77 R37.2@14885.58,3743.77
PC1: J2.16 R34.2 U1.16 | length 2495
  Top Layer w6: U1.16@13641.48,4499.01 13595.08,4499.01 13512.58,4416.51 13512.58,3704.11 13598.79,3617.9 13626.79,3617.9 13670.58,3574.11 13670.58,3511.11 13765.15,3416.54 J2.16@13765.15,3366.57
  Bottom Layer w6: J2.16@13765.15,3366.57 13874.69,3476.11 14274.58,3476.11 14317.58,3519.11 14317.58,3625.11 14357.58,3665.11 14590.58,3665.11 14672.24,3746.77 R34.2@14706.58,3746.77
PC2: J2.17 U1.17 | length 1495.1
  Top Layer w6: U1.17@13641.48,4479.41 13595.28,4479.41 13526.58,4410.71 13526.58,3719.11 13613.79,3631.9 13728.79,3631.9 13768.58,3592.11 13768.58,3508.11 13812.58,3464.11 13812.58,3319.14 J2.17@13865.15,3266.57
PC3: J2.18 U1.18 | length 1398.9
  Top Layer w6: U1.18@13641.48,4459.71 13595.38,4459.71 13540.58,4404.91 13540.58,3742.11 13635.58,3647.11 13810.58,3647.11 13865.15,3592.54 J2.18@13865.15,3366.57
PC4: J2.33 U1.33 | length 1615.4
  Top Layer w6: U1.33@13848.17,4253.01 13848.17,3883.51 13967.57,3764.12 14463.59,3764.1 14567.58,3660.11 14567.58,3511.11 14618.58,3460.11 14618.58,3313.14 J2.33@14665.15,3266.57
PC5: J2.34 U1.34 | length 1559.4
  Top Layer w6: U1.34@13867.88,4253.01 13867.88,3893.81 13983.57,3778.11 14568.59,3778.1 14665.15,3681.54 J2.34@14665.15,3366.57
PC6: J1.13 U1.63 | length 1744.6
  Top Layer w6: U1.63@14251.67,4558.11 14455.41,4558.11 14641.58,4744.28 14641.58,4958.28 15040.58,5357.28 15040.58,5542.11 14972.58,5610.11 14940.58,5610.11 14912.58,5638.11 14912.58,5717.73 J1.13@14865.15,5765.15
PC7: J1.14 J3.2 U1.64 | length 2663.9
  Top Layer w6: U1.64@14251.67,4577.81 14294.68,4577.81 14300.38,4572.11 14442.41,4572.11 14617.58,4747.28 14617.58,4966.28 15021.58,5370.28 15021.58,5533.11 14966.02,5588.66 14911.02,5588.66 14865.15,5634.54 J1.14@14865.15,5665.15
  Bottom Layer w6: J3.2@13959.5,5460.43 13959.5,5518.04 14033.58,5592.11 14820.58,5592.11 14865.15,5636.69 J1.14@14865.15,5665.15
PC8: J1.15 U1.65 | length 1739.4
  Top Layer w6: U1.65@14251.67,4597.51 14294.78,4597.51 14306.18,4586.11 14431.41,4586.11 14594.58,4749.28 14594.58,4974.28 15002.58,5382.28 15002.58,5523.11 14962.58,5563.11 14892.58,5563.11 14813.58,5642.11 14813.58,5716.73 J1.15@14765.15,5765.15
PC9: J1.16 U1.66 | length 1610.9
  Top Layer w6: U1.66@14251.67,4617.21 14294.88,4617.21 14311.98,4600.11 14420.41,4600.11 14570.58,4750.28 14570.58,4983.11 14983.58,5396.11 14983.58,5513.11 14955.58,5541.11 14876.57,5541.12 14765.15,5652.54 J1.16@14765.15,5665.15
PC10: J1.28 U1.78 | length 812.1
  Top Layer w6: U1.78@14143.48,4863.21 14143.48,5358.04 14148.58,5363.14 14148.58,5577.11 14166.58,5595.11 14166.58,5663.73 J1.28@14165.15,5665.15
PC11: J1.29 U1.79 | length 934.3
  Top Layer w6: J1.29@14065.15,5765.15 14114.58,5715.73 14114.58,5615.11 14133.58,5596.11 14133.58,5377.11 14123.77,5367.31 U1.79@14123.77,4863.21
PC12: J1.30 U1.80 | length 829.2
  Top Layer w6: J1.30@14065.15,5665.15 14065.15,5619.54 14117.58,5567.11 14117.58,5401.11 14104.08,5387.61 U1.80@14104.08,4863.21
PC13: J2.7 R6.1 U1.7 | length 3133.6
  Top Layer w6: v3(12974.58,4810.11) 13435.95,4810.11 13569.85,4676.21 U1.7@13641.48,4676.21
  Bottom Layer w6: R6.1@12763.85,3288.11 12913.58,3288.11 12998.58,3203.11 13301.69,3203.11 J2.7@13365.15,3266.57 13311.58,3320.14 13311.58,3390.11 13196.58,3505.11 13196.58,3849.91 12922.58,4123.91 12922.58,4758.11 v3(12974.58,4810.11)
  other v3: 12974.58,4810.11
PC14/LEXT_IN: R22.1 R24.1 U1.8 | length 506.3
  Top Layer w6: R22.1@13418.54,4736.15 13418.54,4738.08 13433.61,4738.08 v3(13480.97,4690.72) 13515.17,4656.51 U1.8@13641.48,4656.51
  Bottom Layer w6: R24.1@13363.69,4864.11 13407.58,4864.11 13480.97,4790.72 v3(13480.97,4690.72)
PC14_E: J2.8 R24.2 | length 1978.6
  Bottom Layer w6: R24.2@13319.3,4864.11 13067.58,4864.11 12939.58,4736.11 12939.58,4131.91 13216.58,3854.91 13216.58,3515.14 J2.8@13365.15,3366.57
PC15/LEXT_OUT: R23.1 R25.1 U1.9 | length 447.7
  Top Layer w6: R23.1@13419.57,4672.11 v3(13454.58,4672.11) 13489.88,4636.81 U1.9@13641.48,4636.81
  Bottom Layer w6: R25.1@13362.69,4810.11 13422.58,4810.11 13454.58,4778.11 v3(13454.58,4672.11)
PC15_E: J2.9 R25.2 | length 2066.3
  Bottom Layer w6: R25.2@13318.3,4810.11 13045.54,4810.08 12953.58,4718.11 12953.58,4138.91 13233.58,3858.91 13233.58,3569.11 13412.58,3390.11 13412.58,3322.11 13465.15,3269.54 J2.9@13465.15,3266.57
PD0: J1.31 U1.81 | length 958.8
  Top Layer w6: J1.31@13965.15,5765.15 14017.58,5712.73 14017.58,5620.39 14008.58,5611.39 14008.58,5368.11 14084.38,5292.31 U1.81@14084.38,4863.21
